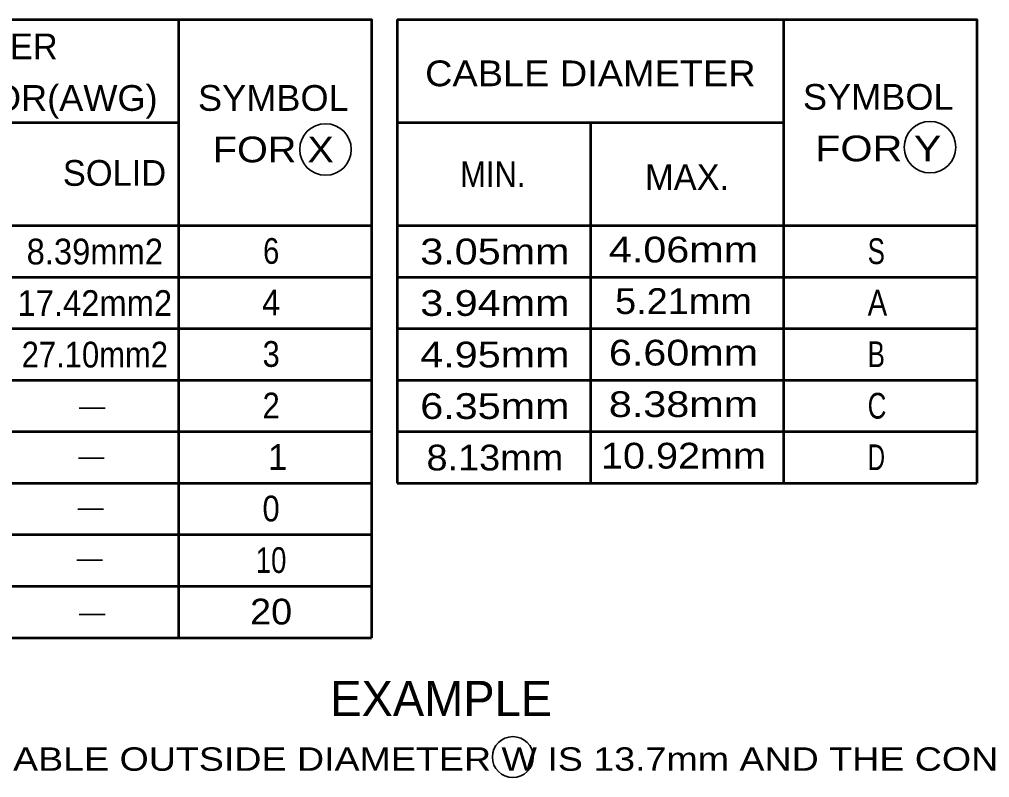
# Model space of a CAD drawing. Extents: x -32 to 824, y -6 to 538.
# Drawn here: x 605.1 to 704.6, y 343.6 to 421.3 of the extents above; entities that cross this region are included whole.
import ezdxf
from ezdxf.enums import TextEntityAlignment as Align

# ---------------------------------------------------------------- set-up
doc = ezdxf.new("R2010")
doc.units = 0
doc.header["$LTSCALE"] = 1.1
doc.layers.add('1', color=7, linetype='Continuous', lineweight=53)

msp = doc.modelspace()

# ---------------------------------------------------------------- linework, layer by layer
at = {"layer": '1'}
for p, q in [((621.409, 421.292), (621.409, 357.932)), ((643.849, 421.292), (643.849, 373.772)), ((683.449, 421.292), (683.449, 373.772)), ((581.809, 410.732), (621.409, 410.732)), ((643.849, 410.732), (683.449, 410.732)), ((663.649, 410.732), (663.649, 373.772)), ((581.809, 400.172), (641.209, 400.172)), ((643.849, 400.172), (703.249, 400.172)), ((581.809, 394.892), (641.209, 394.892)), ((643.849, 394.892), (703.249, 394.892)), ((581.809, 389.612), (641.209, 389.612)), ((643.849, 389.612), (703.249, 389.612)), ((581.809, 384.332), (641.209, 384.332)), ((643.849, 384.332), (703.249, 384.332)), ((581.809, 379.052), (641.209, 379.052)), ((643.849, 379.052), (703.249, 379.052)), ((581.809, 373.772), (641.209, 373.772)), ((643.849, 373.772), (703.249, 373.772)), ((581.809, 368.492), (641.209, 368.492)), ((581.809, 363.212), (641.209, 363.212)), ((581.809, 357.932), (641.209, 357.932))]:
    msp.add_line(p, q, dxfattribs=at)
at = {"layer": '1', "lineweight": 35}
for p, q in [((611.246, 381.447), (613.886, 381.447)), ((611.163, 376.312), (613.803, 376.312)), ((611.081, 371.092), (613.721, 371.092)), ((611, 365.872), (613.639, 365.872)), ((611.244, 360.325), (613.884, 360.325))]:
    msp.add_line(p, q, dxfattribs=at)
at = {"layer": '1'}
for points in [[(581.809, 421.292), (641.209, 421.292), (641.209, 357.932)], [(643.849, 421.292), (703.249, 421.292), (703.249, 373.772)]]:
    msp.add_lwpolyline(points, dxfattribs=at)
at = {"layer": '1', "lineweight": 35}
for centre, radius in [((698.459, 408.196), 2.64), ((636.488, 407.964), 2.64), ((655.69, 345.695), 2.1)]:
    msp.add_circle(centre, radius, dxfattribs=at)

# ---------------------------------------------------------------- texts
at = {"layer": '1'}
for s, p in [('COPPER', (601.575, 417.201)), ('1', (631.584, 375.125))]:
    msp.add_text(s, height=2.64, dxfattribs=at).set_placement(p, align=Align.CENTER)
for s, height, width, p in [('CABLE DIAMETER', 2.64, 1.1, (646.697, 414.444)), ('MIN.', 2.64, 0.9, (650.287, 404.102)), ('S', 2.64, 0.75, (692.069, 396.22)), ('A', 2.64, 0.85, (692.069, 390.94)), ('B', 2.64, 0.75, (692.069, 385.66)), ('C', 2.64, 0.75, (692.069, 380.38)), ('D', 2.64, 0.7, (692.069, 375.1)), ('IF THE LINE SIDE CABLE OUTSIDE DIAMETER W IS 13.7mm AND THE CONDUCTOR', 2.4, 1.2, (568.716, 344.295))]:
    msp.add_text(s, height=height, dxfattribs=dict(at, width=width)).set_placement(p)
for s, width, p in [('CONDUCTOR(AWG)', 1.05, (601.565, 411.921)), ('SYMBOL', 1.05, (631.137, 411.923)), ('SYMBOL', 1.05, (693.157, 412.029)), ('FOR X', 1.15, (631.137, 406.643)), ('FOR Y', 1.2, (693.156, 406.749)), ('8.39mm2', 0.95, (612.836, 396.183)), ('6', 0.85, (630.916, 396.245)), ('3.05mm', 1.2, (653.851, 396.189)), ('4.06mm', 1.2, (673.187, 396.384)), ('17.42mm2', 0.95, (612.836, 390.903)), ('4', 0.95, (630.916, 390.965)), ('3.94mm', 1.2, (653.851, 390.909)), ('5.21mm', 1.1, (673.187, 391.104)), ('27.10mm2', 0.9, (612.836, 385.623)), ('3', 0.9, (630.916, 385.685)), ('4.95mm', 1.2, (653.851, 385.629)), ('6.60mm', 1.2, (673.187, 385.824)), ('2', 0.9, (630.916, 380.405)), ('6.35mm', 1.2, (653.851, 380.349)), ('8.38mm', 1.2, (673.187, 380.544)), ('8.13mm', 1.1, (653.851, 375.069)), ('10.92mm', 1.15, (673.187, 375.264)), ('0', 0.9, (630.906, 369.845)), ('10', 0.8, (630.906, 364.565)), ('20', 1.1, (630.906, 359.285))]:
    msp.add_text(s, height=2.64, dxfattribs=dict(at, width=width)).set_placement(p, align=Align.CENTER)
for s, height, p in [('SOLID', 2.64, (609.557, 404.239)), ('MAX.', 2.64, (669.24, 403.815)), ('EXAMPLE', 3.6, (636.97, 349.899))]:
    msp.add_text(s, height=height, dxfattribs=at).set_placement(p)

doc.saveas('drawing.dxf')
